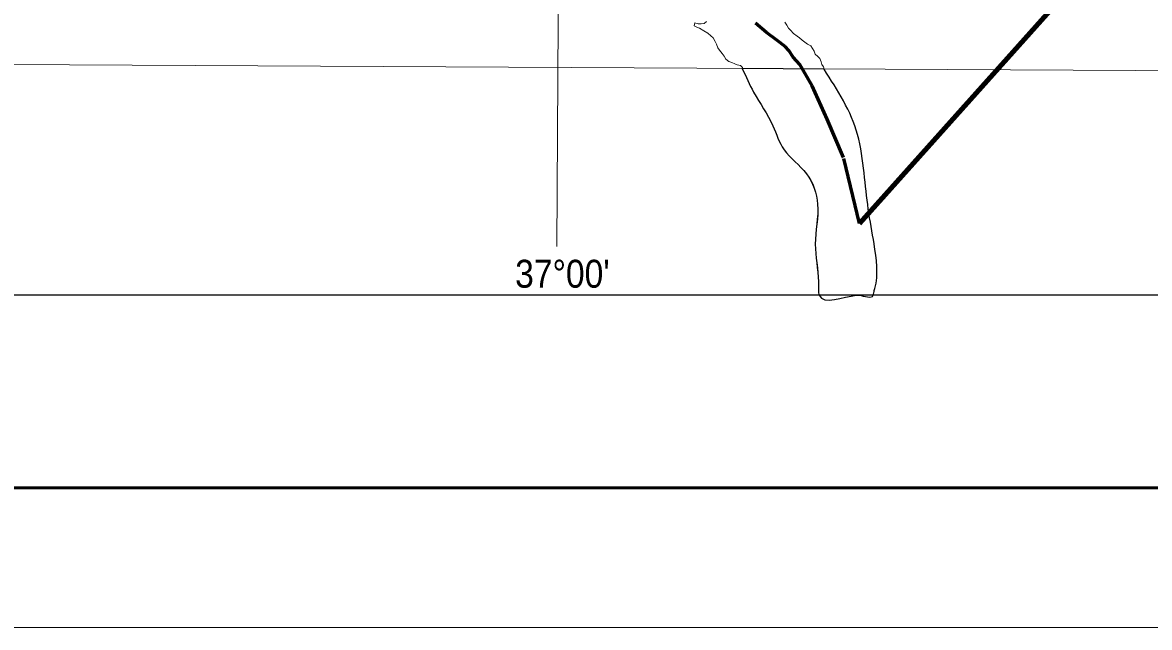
# Model space of a CAD drawing. Extents: x 553962 to 842807, y 8883888 to 9032388.
# Drawn here: x 709644 to 729831, y 8883888 to 8894722 of the extents above; entities that cross this region are included whole.
import ezdxf
from ezdxf.enums import TextEntityAlignment as Align

# ---------------------------------------------------------------- set-up
doc = ezdxf.new("R2010")
doc.units = 0
doc.header["$LTSCALE"] = 200
doc.linetypes.add('LONG_DASH_SHORT_DASH', pattern=[9.9, 6, -1.2, 1.5, -1.2])
for name, color, linetype, lineweight in [('1', 7, 'Continuous', 13), ('25', 7, 'Continuous', 13), ('3', 7, 'Continuous', 13), ('7', 7, 'Continuous', 90), ('9', 7, 'Continuous', 90)]:
    doc.layers.add(name, color=color, linetype=linetype, lineweight=lineweight)
doc.layers.add('46', color=7, linetype='Continuous')

msp = doc.modelspace()

# ---------------------------------------------------------------- linework, layer by layer
at = {"layer": '1'}
for points in [[(719978.9, 9023574.5), (719561.6, 8949232.2), (719215.6, 8890710.6)], [(564751.7, 8894587.5), (664411.9, 8894209.9), (791388.5, 8893536.2)]]:
    msp.add_lwpolyline(points, dxfattribs=at)
at = {"layer": '25', "lineweight": 25}
msp.add_line((724002.8, 8893886.5), (722537.3, 8893896.5), dxfattribs=at)
msp.add_line((724002.8, 8893886.5), (722537.3, 8893896.5), dxfattribs=at)
at = {"layer": '25'}
for points in [[(722073.4, 8894336.8), (722053.4, 8894382.8), (722013.2, 8894449.3), (721972.7, 8894485.2), (721917.1, 8894531.4), (721846.2, 8894572.6), (721770.2, 8894618.9), (721724.6, 8894639.6), (721673.9, 8894665.4), (721689.5, 8894716.2), (721745.3, 8894700.6), (721801.3, 8894700.2), (721852.2, 8894705), (721893.1, 8894740.4)], [(723301.9, 8894726.3), (723337.1, 8894675.1), (723367.3, 8894624), (723402.6, 8894583), (723453.1, 8894526.7), (723518.8, 8894475.3), (723564.4, 8894449.5), (723609.9, 8894408.5), (723655.5, 8894372.5), (723706.1, 8894336.6), (723761.8, 8894305.6), (723797.1, 8894259.6), (723827.3, 8894208.4), (723842.2, 8894157.4), (723887.6, 8894111.3), (723928.1, 8894075.3), (723948, 8894019.2)], [(722537.3, 8893896.5), (722543.5, 8893916.1), (722503.1, 8893952.1), (722447.2, 8893962.6), (722401.6, 8893983.3), (722350.9, 8894004), (722295.1, 8894024.7), (722244.5, 8894065.8), (722214.3, 8894122), (722174, 8894168.1), (722128.6, 8894224.4), (722098.4, 8894270.5), (722073.4, 8894336.8)], [(723948, 8894019.2), (723962.9, 8893968.2), (723993.2, 8893927.2), (724002.8, 8893886.5), (722537.3, 8893896.5)]]:
    msp.add_lwpolyline(points, dxfattribs=at)
at = {"layer": '25', "lineweight": 25}
for points in [[(722537.3, 8893896.5), (722740.6, 8893475.5), (723084.4, 8892873.8), (723285, 8892444), (723686.1, 8892014.3), (723886.7, 8891469.9), (723843.7, 8890753.6), (723901, 8890080.3), (723900.8, 8889934.8), (723915.3, 8889836.7), (724574.3, 8889836.7), (724631.6, 8889836.7), (724883.2, 8889836.5), (724893.2, 8889883.7), (724911.8, 8889958.1), (724898, 8890758.3), (724794.3, 8891380.3), (724717.6, 8892028.6), (724603, 8892716.2), (724002.8, 8893886.5)], [(722537.3, 8893896.5), (722740.6, 8893475.5), (723084.4, 8892873.8), (723285, 8892444), (723686.1, 8892014.3), (723886.7, 8891469.9), (723843.7, 8890753.6), (723901, 8890080.3), (723901.3, 8889998.4)], [(724811.6, 8891262.3), (724794.3, 8891380.3), (724717.6, 8892028.6), (724603, 8892716.2), (724002.8, 8893886.5)]]:
    msp.add_spline(points, degree=3, dxfattribs=at)
at = {"layer": '3'}
msp.add_lwpolyline([(842807.3, 9032387.8), (842807.3, 8883887.8), (553961.7, 8883887.8), (553961.7, 9032387.8)], close=True, dxfattribs=at)
at = {"layer": '3', "lineweight": 53}
msp.add_lwpolyline([(840307.3, 9029887.8), (840307.3, 8886387.8), (560211.7, 8886387.8), (560211.7, 9029887.8)], close=True, dxfattribs=at)
at = {"layer": '3', "lineweight": 25}
msp.add_lwpolyline([(563033.9, 9026438.8), (793061.1, 9026438.8), (793495.6, 8889836.8), (563468.3, 8889836.8)], close=True, dxfattribs=at)
at = {"layer": '7', "linetype": 'LONG_DASH_SHORT_DASH', "lineweight": 60}
msp.add_lwpolyline([(724638.9, 8891123.6), (724349.6, 8892305.9), (724059.6, 8892992.2), (723788.9, 8893591.5), (723566.6, 8893968.5), (723450.6, 8894103.8), (723373.3, 8894219.2), (723307.3, 8894290.7), (723154.9, 8894408.1), (722972, 8894546), (722773.8, 8894710.7)], dxfattribs=at)
at = {"layer": '9'}
msp.add_lwpolyline([(724638.9, 8891123.6), (729122.2, 8896139.1), (740717.5, 8896813.6), (741371.9, 8898310.2)], dxfattribs=at)

# ---------------------------------------------------------------- texts
at = {"layer": '46', "width": 0.9}
msp.add_text("37°00'", height=500, dxfattribs=at).set_placement((719315, 8889973.1), align=Align.CENTER)

doc.saveas('drawing.dxf')
